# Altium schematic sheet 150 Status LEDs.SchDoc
size Letter; Organization: Toradex Solutions Inc.; Address1: 6415 Northwest Drive; Address2: Mississauga, ON, L4V 1X1; Address3: Canada
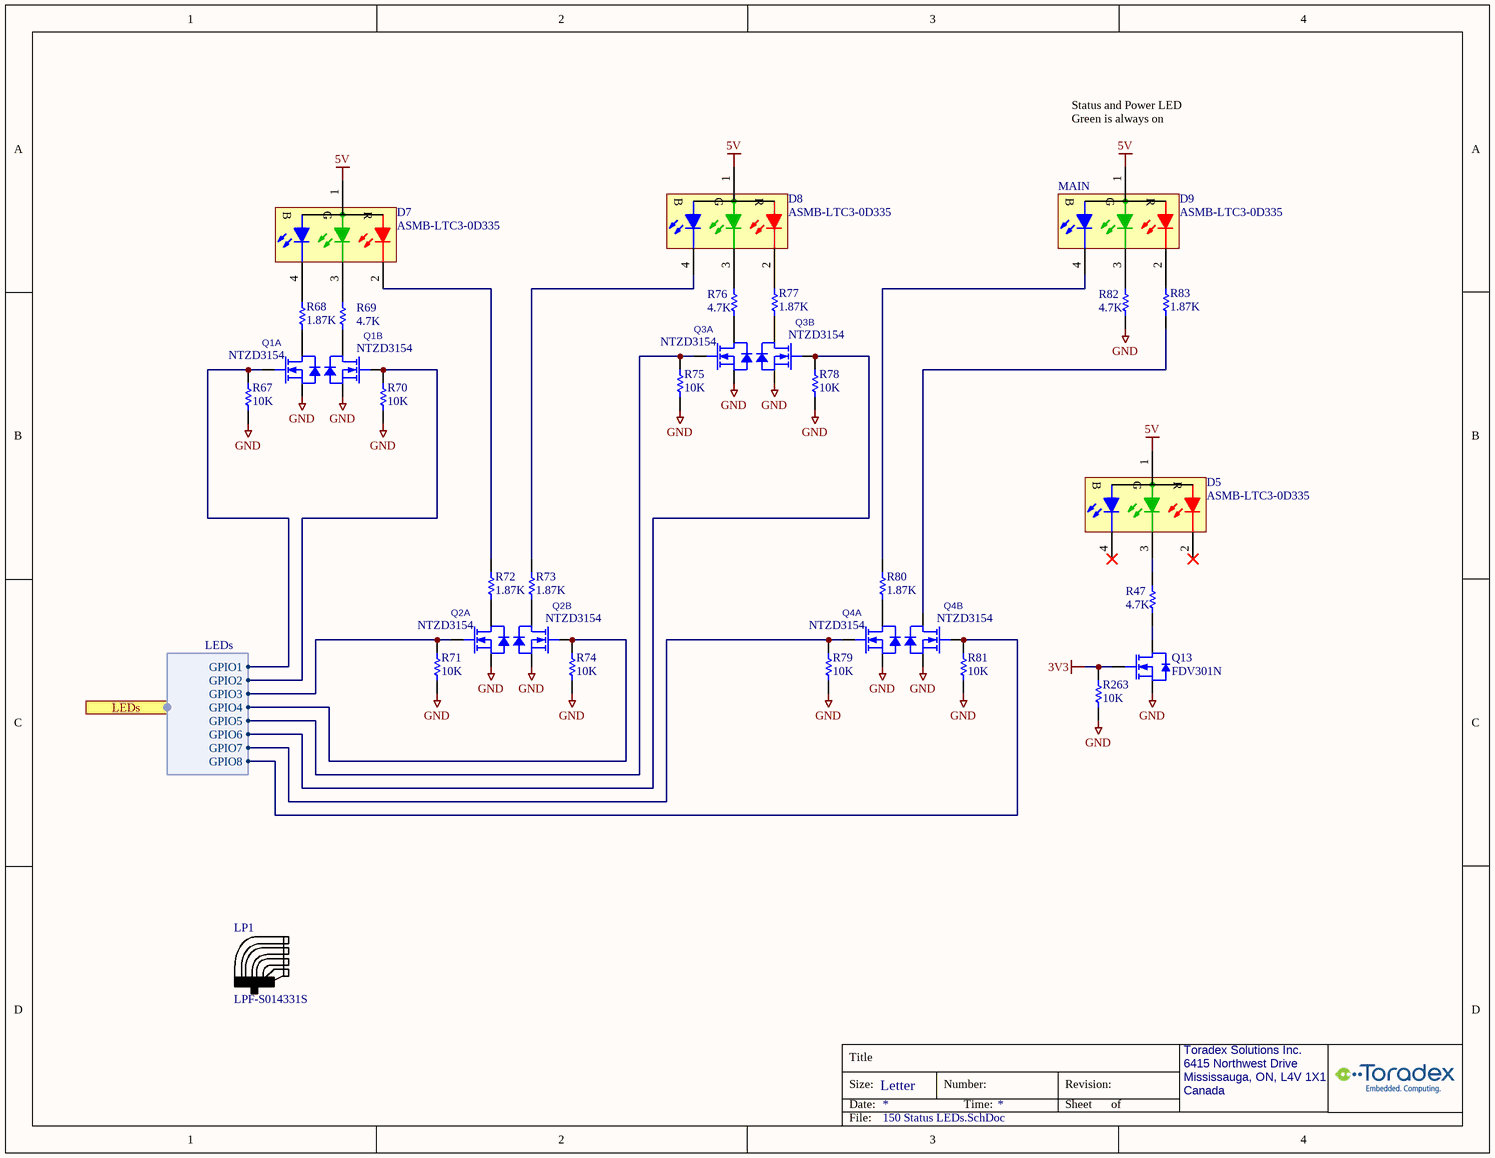
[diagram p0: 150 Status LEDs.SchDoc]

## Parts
D5  ASMB-LTC3-0D335  [4-PLCC_LED_2121_BROADCOM]
D7  ASMB-LTC3-0D335  [4-PLCC_LED_2121_BROADCOM]
D8  ASMB-LTC3-0D335  [4-PLCC_LED_2121_BROADCOM]
D9  ASMB-LTC3-0D335  [4-PLCC_LED_2121_BROADCOM]
LP1  LPF-S014331S  [LPF-S014331S]
Q1  NTZD3154  [SOT563]  (parts A,B of 2)
Q2  NTZD3154  [SOT563]  (parts A,B of 2)
Q3  NTZD3154  [SOT563]  (parts A,B of 2)
Q4  NTZD3154  [SOT563]  (parts A,B of 2)
Q13  FDV301N  [SOT23]
R47  value 4.7K  [R0402_RESC1005L]  (hidden comment: 2233-Res-0402-4.7K)
R67  value 10K  [R0402_RESC1005L]  (hidden comment: 1572-Res-0402-10K)
R68  value 1.87K  [R0402_RESC1005L]  (hidden comment: 1536-Res-0402-1.87K)
R69  value 4.7K  [R0402_RESC1005L]  (hidden comment: 2233-Res-0402-4.7K)
R70  value 10K  [R0402_RESC1005L]  (hidden comment: 1572-Res-0402-10K)
R71  value 10K  [R0402_RESC1005L]  (hidden comment: 1572-Res-0402-10K)
R72  value 1.87K  [R0402_RESC1005L]  (hidden comment: 1536-Res-0402-1.87K)
R73  value 1.87K  [R0402_RESC1005L]  (hidden comment: 1536-Res-0402-1.87K)
R74  value 10K  [R0402_RESC1005L]  (hidden comment: 1572-Res-0402-10K)
R75  value 10K  [R0402_RESC1005L]  (hidden comment: 1572-Res-0402-10K)
R76  value 4.7K  [R0402_RESC1005L]  (hidden comment: 2233-Res-0402-4.7K)
R77  value 1.87K  [R0402_RESC1005L]  (hidden comment: 1536-Res-0402-1.87K)
R78  value 10K  [R0402_RESC1005L]  (hidden comment: 1572-Res-0402-10K)
R79  value 10K  [R0402_RESC1005L]  (hidden comment: 1572-Res-0402-10K)
R80  value 1.87K  [R0402_RESC1005L]  (hidden comment: 1536-Res-0402-1.87K)
R81  value 10K  [R0402_RESC1005L]  (hidden comment: 1572-Res-0402-10K)
R82  value 4.7K  [R0402_RESC1005L]  (hidden comment: 2233-Res-0402-4.7K)
R83  value 1.87K  [R0402_RESC1005L]  (hidden comment: 1536-Res-0402-1.87K)
R263  value 10K  [R0402_RESC1005L]  (hidden comment: 1572-Res-0402-10K)

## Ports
LEDs (harness LEDs)

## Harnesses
LEDs: GPIO1, GPIO2, GPIO3, GPIO4, GPIO5, GPIO7, GPIO8, GPIO6

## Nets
3V3: Q13.1(G) R263.2
5V: D5.1(A1) D7.1(A1) D8.1(A1) D9.1(A1)
GND: Q1.1(S) Q1.4(S) Q2.1(S) Q2.4(S) Q3.1(S) Q3.4(S) Q4.1(S) Q4.4(S) Q13.2(S) R67.1 R70.1 R71.1 R74.1 R75.1 R78.1 R79.1 R81.1 R82.1 R263.1
NetD5_3: D5.3(K2) R47.2
NetD7_2: D7.2(K3) R72.2
NetD7_3: D7.3(K2) R69.2
NetD7_4: D7.4(K1) R68.2
NetD8_2: D8.2(K3) R77.2
NetD8_3: D8.3(K2) R76.2
NetD8_4: D8.4(K1) R73.2
NetD9_2: D9.2(K3) R83.2
NetD9_3: D9.3(K2) R82.2
NetD9_4: D9.4(K1) R80.2
NetQ1_2: Q1.2(G) R67.2 ; port LEDs.GPIO1
NetQ1_3: Q1.3(D) R69.1
NetQ1_5: Q1.5(G) R70.2 ; port LEDs.GPIO2
NetQ1_6: Q1.6(D) R68.1
NetQ2_2: Q2.2(G) R71.2 ; port LEDs.GPIO3
NetQ2_3: Q2.3(D) R73.1
NetQ2_5: Q2.5(G) R74.2 ; port LEDs.GPIO4
NetQ2_6: Q2.6(D) R72.1
NetQ3_2: Q3.2(G) R75.2 ; port LEDs.GPIO5
NetQ3_3: Q3.3(D) R77.1
NetQ3_5: Q3.5(G) R78.2 ; port LEDs.GPIO6
NetQ3_6: Q3.6(D) R76.1
NetQ4_2: Q4.2(G) R79.2 ; port LEDs.GPIO7
NetQ4_3: Q4.3(D) R83.1
NetQ4_5: Q4.5(G) R81.2 ; port LEDs.GPIO8
NetQ4_6: Q4.6(D) R80.1
NetQ13_3: Q13.3(D) R47.1

Not connected (* = marked no-connect by the designer): D5 2(K3)* 4(K1)*

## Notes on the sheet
- Status and Power LED
- Green is always on
- (near D9) MAIN

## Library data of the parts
D5 D7-D9 = 2349-LED RGB 4SMD: (-40 to 85 DegC) LED RGB 2.1mm x 1.9mm x 1mm 4SMD vf=2V Red, 2.6V Green, 2.7V Blue; Mfr: Broadcom; PN: 2349
LP1 = 2302-Lightpipe Lumex LPF-S014331S: Lightpipe R/A for 1210 size LEDs. 3.2mm x 1.8mm lens size. Board mount, press fit.; Mfr: Lumex; PN: 2302
Q1-Q4 = 1146-NTZD3154NT1G: (-55 to 150 DegC) MOSFET 2N-CH (dual) 20V 0.54A SOT-563 1.6x1.6mm Vth:1V Ron typ:400m@4.5V, 500m@2.5V, 700m@1.8V; Mfr: ON Semiconductor; PN: 1146; Alt: NTZD3154NT5G,PMDT290UNE,115
Q13 = 0761-FDV301N: (-55 to 155 DegC) MOSFET N-CH 25V 220MA SOT-23 Vth:1.1V Ron typ:4ohm@3V Vgsm:8V; Mfr: Fairchild/ON Semiconductor; PN: 761; DR: FDV301NDKR-ND; TR: FDV301NTR-ND; Alt: DMN62D0U-13, DMN62D0U-7, DMN61D9U-7
R47 R69 R76 R82 = 2233-Res-0402-4.7K: (-55 to 155 DegC) RES 4.70K OHM 1/16W 1% 0402 100ppm; MfrNo: RC0402FR-074K7L; Mfr: Yageo; PN: 2233
R67 R70 R71 R74 R75 R78 R79 R81 R263 = 1572-Res-0402-10K: (-55 to 155 DegC AEC) RES 10K OHM 1% 1/16W 100ppm 0402; Mfr: Stackpole Electronics; MfrNo: RMCF0402FT10K0; PN: 1572; Alt: AC0402FR-0710KL,AC0402FR-1310KL,CRGCQ0402F10K
R68 R72 R73 R77 R80 R83 = 1536-Res-0402-1.87K: (-55 to 155 DegC AEC) RES 1.87K OHM 1% 1/16W 100ppm 0402; MfrNo: RMCF0402FT1K87; Mfr: Stackpole Electronics; Alt: AC0402FR-071K87L,RK73H1ETTP1871F,ERJ-2RKF1871X; PN: 1536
